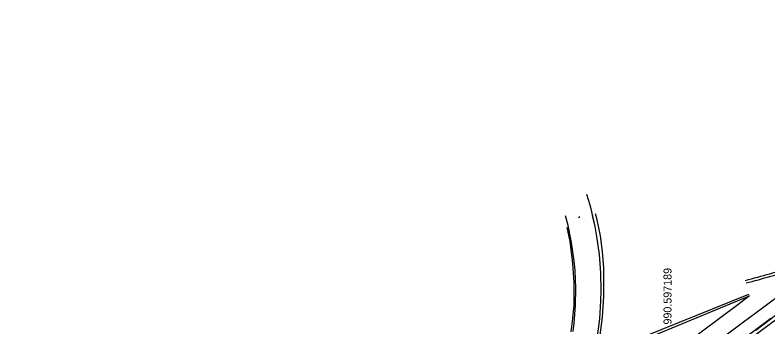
# Model space of a CAD drawing. Extents: x -26 to 1615461, y 490 to 1281970.
# Drawn here: x 1610492 to 1611056, y 1094203 to 1094436 of the extents above; entities that cross this region are included whole.
import ezdxf

# ---------------------------------------------------------------- set-up
doc = ezdxf.new("R2010")
doc.units = 0
for name, color, linetype in [('CLS_P_Shld_Gore', 7, 'Continuous'), ('CLS_Search_Dist', 7, 'Continuous'), ('CLS_Unpave_Sh_Gore', 7, 'Continuous'), ('Level 12', 7, 'Continuous'), ('RD_EX_Road', 7, 'Continuous'), ('RD_EX_Road_EOT', 7, 'Continuous'), ('RD_PD_DR_Inlet', 7, 'Continuous'), ('RD_Sketch2', 7, 'Continuous'), ('RD_Sketch3', 7, 'Continuous'), ('RD_Sketch4', 7, 'Continuous'), ('RD_XS_Greenside', 7, 'Continuous')]:
    doc.layers.add(name, color=color, linetype=linetype)

msp = doc.modelspace()

# ---------------------------------------------------------------- linework, layer by layer
at = {"layer": 'CLS_P_Shld_Gore'}
msp.add_arc((1610842.42, 1094990.54), 780.33, 284.62849, 287.4373, dxfattribs=at)
at = {"layer": 'CLS_Search_Dist'}
msp.add_line((1610963.65, 1094195.61), (1611041.62, 1094227.05), dxfattribs=at)
msp.add_arc((1610842.42, 1094990.54), 778.33, 284.62849, 287.4373, dxfattribs=at)
at = {"layer": 'CLS_Unpave_Sh_Gore'}
msp.add_line((1610966.61, 1094194.54), (1611042.02, 1094225.83), dxfattribs=at)
at = {"layer": 'RD_EX_Road'}
for points in [[(1610901.22, 1094112.65), (1610905.97, 1094121.36), (1610905.86, 1094122.38), (1610909.93, 1094131.71), (1610916.92, 1094150.5), (1610922.62, 1094169.73), (1610926.94, 1094188.83), (1610928.44, 1094197.42), (1610929.84, 1094208.74), (1610930.78, 1094222.24), (1610930.95, 1094229.63), (1610930.67, 1094243.23), (1610929.6, 1094256.8), (1610927.75, 1094270.28), (1610926.39, 1094277.82), (1610924.52, 1094286.06)], [(1610904.03, 1094286.19), (1610905.7, 1094279.79), (1610905.87, 1094278.91)], [(1610930.08, 1094194.29), (1610931.85, 1094209.79), (1610932.84, 1094225.35), (1610933.03, 1094240.94), (1610932.9, 1094246.94), (1610932.05, 1094258.99), (1610930.41, 1094270.96), (1610927.99, 1094282.8), (1610926.75, 1094287.43)], [(1610905.35, 1094277.06), (1610906.78, 1094270.09), (1610907.37, 1094266.5), (1610909.22, 1094252.39), (1610909.45, 1094250.02), (1610910.37, 1094235.82), (1610910.5, 1094231.32), (1610910.43, 1094225.16), (1610910.36, 1094218.97), (1610909.3, 1094206.91), (1610908.29, 1094198.87)], [(1610906.01, 1094278.22), (1610908.5, 1094265.88), (1610910.52, 1094251.84), (1610911.14, 1094244.91), (1610911.71, 1094231.76), (1610911.49, 1094218.61), (1610910.47, 1094205.49), (1610909.78, 1094199.07)], [(1611068.59, 1094229.1), (1611051.93, 1094216.71), (1611037.63, 1094206.09), (1611022.53, 1094194.8)], [(1611058.02, 1094208.87), (1611041, 1094196.11), (1611023.02, 1094182.69), (1611004.7, 1094168.97), (1610987.52, 1094156.06), (1610969.88, 1094142.68), (1610952.19, 1094129.36), (1610939.26, 1094119.68), (1610929.6, 1094112.49), (1610916.44, 1094102.81), (1610911.19, 1094099.02)]]:
    msp.add_lwpolyline(points, dxfattribs=at)
at = {"layer": 'RD_EX_Road_EOT'}
msp.add_line((1610913.98, 1094284.7), (1610914.87, 1094285.45), dxfattribs=at)
for points in [[(1610928.44, 1094197.42), (1610929.84, 1094208.74), (1610930.78, 1094222.24), (1610930.95, 1094229.63), (1610930.67, 1094243.23), (1610929.6, 1094256.8), (1610927.75, 1094270.28), (1610926.39, 1094277.82), (1610923.35, 1094291.18), (1610922.68, 1094293.75), (1610920.22, 1094301.93)], [(1610904.03, 1094286.19), (1610905.7, 1094279.79), (1610908.5, 1094265.88), (1610910.52, 1094251.84), (1610911.14, 1094244.91), (1610911.71, 1094231.76), (1610911.49, 1094218.61), (1610910.47, 1094205.49), (1610909.78, 1094199.07)], [(1611058.02, 1094208.87), (1611041, 1094196.11)]]:
    msp.add_lwpolyline(points, dxfattribs=at)
at = {"layer": 'RD_PD_DR_Inlet'}
for p, q in [((1611042.02, 1094225.83), (1611033.22, 1094219.17)), ((1611033.22, 1094219.17), (1610971.61, 1094173.37))]:
    msp.add_line(p, q, dxfattribs=at)
at = {"layer": 'RD_Sketch2'}
msp.add_lwpolyline([(1611046.75, 1094200.18), (1611061.61, 1094211.35)], dxfattribs=at)
at = {"layer": 'RD_Sketch3'}
msp.add_line((1611368.88, 1094436.29), (1610191.56, 1093561.12), dxfattribs=at)
at = {"layer": 'RD_Sketch4'}
msp.add_lwpolyline([(1611058.02, 1094208.87), (1611041, 1094196.11), (1611023.02, 1094182.69), (1611004.7, 1094168.97), (1610987.52, 1094156.06), (1610969.88, 1094142.68), (1610952.19, 1094129.36), (1610939.26, 1094119.68), (1610929.6, 1094112.49), (1610916.44, 1094102.81), (1610903.67, 1094093.6), (1610891.53, 1094084.58), (1610879.73, 1094075.78), (1610865.72, 1094065.38)], dxfattribs=at)
at = {"layer": 'RD_XS_Greenside'}
msp.add_arc((1609417.39, 1092424.22), 2020, 56.13007, 81.50654, dxfattribs=at)

# ---------------------------------------------------------------- texts
at = {"layer": 'Level 12'}
msp.add_text('990.597189', height=6, rotation=90, dxfattribs=at).set_placement((1610983.66, 1094204.38))

doc.saveas('drawing.dxf')
